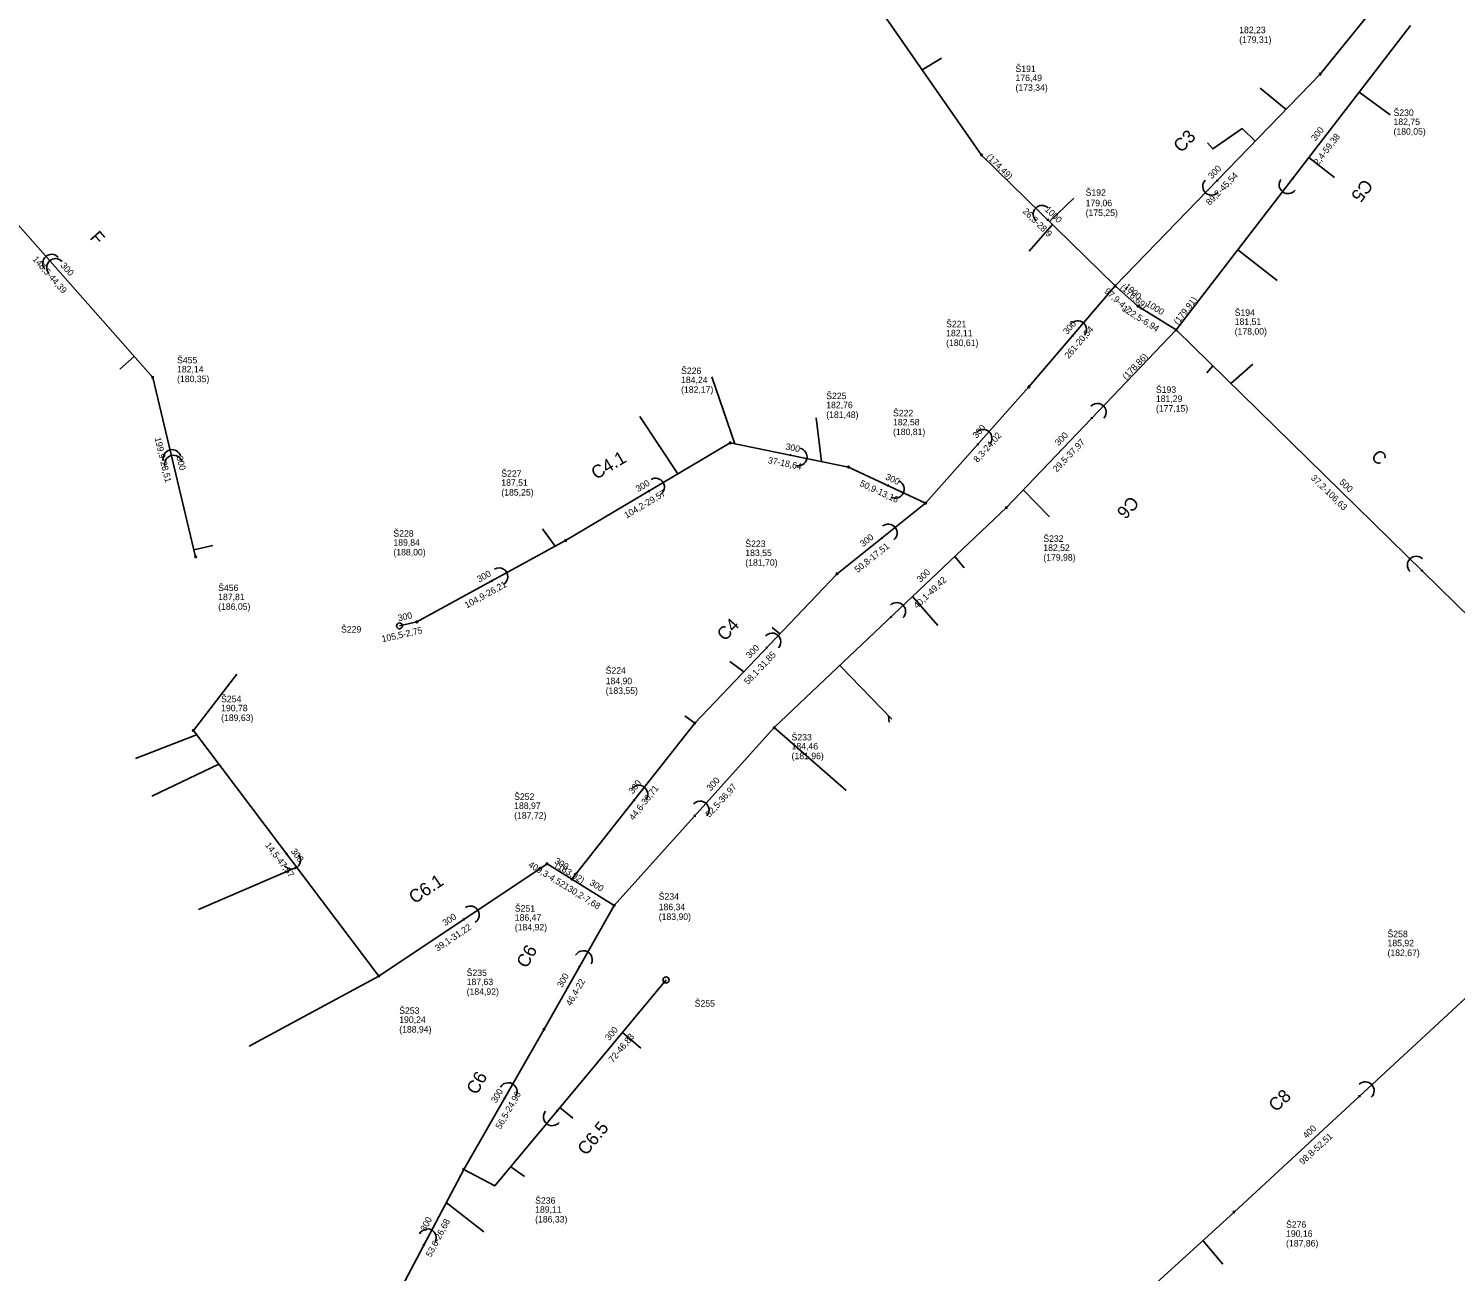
# Model space of a CAD drawing. Extents: x -548529 to -543591, y -1201432 to -1192608.
# Drawn here: x -547490.5 to -547270, y -1195800.5 to -1195608.4 of the extents above; entities that cross this region are included whole.
import ezdxf

# ---------------------------------------------------------------- set-up
doc = ezdxf.new("R2010")
doc.units = 0
for name, color, linetype in [('C3D_Bod-Značky', 7, 'Continuous'), ('C3D_Koridor', 7, 'Continuous'), ('C3D_Křižovatka', 7, 'Continuous'), ('C3D_Netisknutelná', 7, 'Continuous'), ('C3D_Podsestava', 7, 'Continuous'), ('C3D_PP-zobrazeni v PR', 7, 'Continuous'), ('C3D_PR-Popisek', 7, 'Continuous'), ('C3D_SPR-Popisek', 7, 'Continuous'), ('C3D_Tlakove_potrubi_Popis', 7, 'Continuous'), ('C3D_ZPR-Formaty', 7, 'Continuous')]:
    doc.layers.add(name, color=color, linetype=linetype)

# ---------------------------------------------------------------- blocks, each defined once
blk = doc.blocks.new('100')
at = {"layer": 'Defpoints'}
blk.add_circle((0, 0), 0.127, dxfattribs=at)
blk = doc.blocks.new('101')
at = {"layer": 'Defpoints'}
blk.add_circle((0, 0), 0.463, dxfattribs=at)
blk = doc.blocks.new('86')
at = {"layer": 'Defpoints'}
blk.add_lwpolyline([(0.08, 0.14), (0.19, 0), (0.08, -0.14)], dxfattribs=at)
blk.add_arc((1.37, 0), 1.37, 270, 90, dxfattribs=at)
blk = doc.blocks.new('91')
at = {"layer": 'Defpoints'}
blk.add_lwpolyline([(0.08, 0.14), (0.19, 0), (0.08, -0.14)], dxfattribs=at)
blk.add_arc((1.37, 0), 1.37, 270, 90, dxfattribs=at)
blk = doc.blocks.new('88')
at = {"layer": 'Defpoints'}
for centre in [(0.47, 0), (1.37, 0)]:
    blk.add_arc(centre, 1.37, 270, 90, dxfattribs=at)

msp = doc.modelspace()

# ---------------------------------------------------------------- linework, layer by layer
at = {"layer": 'C3D_Bod-Značky'}
for points in [[(-547343.222, -1195627.948), (-547378.023, -1195577.949)], [(-547261.272, -1195578.867), (-547290.91, -1195615.433)], [(-547276.928, -1195607.929), (-547313.169, -1195654.962)], [(-547290.91, -1195615.433), (-547322.568, -1195648.165)], [(-547322.568, -1195648.165), (-547343.222, -1195627.948)], [(-547335.918, -1195663.777), (-547322.568, -1195648.165)], [(-547319.066, -1195651.296), (-547322.568, -1195648.165)], [(-547313.169, -1195654.962), (-547319.066, -1195651.296)], [(-547339.386, -1195682.43), (-547313.169, -1195654.962)], [(-547237.001, -1195729.585), (-547313.169, -1195654.962)], [(-547351.862, -1195681.742), (-547335.918, -1195663.777)], [(-547407.485, -1195687.504), (-547382.048, -1195672.428)], [(-547382.048, -1195672.428), (-547363.782, -1195676.159)], [(-547363.782, -1195676.159), (-547351.862, -1195681.742)], [(-547375.25, -1195716.43), (-547339.386, -1195682.43)], [(-547365.556, -1195692.655), (-547351.862, -1195681.742)], [(-547430.477, -1195700.089), (-547407.485, -1195687.504)], [(-547387.512, -1195715.73), (-547365.556, -1195692.655)], [(-547433.16, -1195700.702), (-547430.477, -1195700.089)], [(-547406.517, -1195739.851), (-547387.512, -1195715.73)], [(-547399.992, -1195743.898), (-547375.25, -1195716.43)], [(-547465.003, -1195716.865), (-547436.327, -1195754.821)], [(-547436.327, -1195754.821), (-547410.36, -1195737.48)], [(-547410.36, -1195737.48), (-547406.517, -1195739.851)], [(-547406.517, -1195739.851), (-547399.992, -1195743.898)], [(-547410.818, -1195763.055), (-547399.992, -1195743.898)], [(-547391.973, -1195755.423), (-547402.576, -1195768.178), (-547418.429, -1195787.249), (-547423.237, -1195784.702)], [(-547304.215, -1195791.3), (-547265.674, -1195755.643)], [(-547423.237, -1195784.702), (-547410.818, -1195763.055)], [(-547435.695, -1195808.298), (-547423.237, -1195784.702)], [(-547340.806, -1195824.625), (-547304.215, -1195791.3)]]:
    msp.add_lwpolyline(points, dxfattribs=at)
at = {"layer": 'C3D_Koridor'}
for points in [[(-547352.385, -1195614.783), (-547349.399, -1195612.96)], [(-547296.187, -1195620.889), (-547300.174, -1195617.588)], [(-547284.875, -1195618.243), (-547280.095, -1195621.706)], [(-547300.935, -1195625.798), (-547302.956, -1195623.844), (-547307.511, -1195626.987), (-547308.321, -1195626.071)], [(-547292.655, -1195628.339), (-547288.712, -1195631.414)], [(-547332.727, -1195638.221), (-547328.975, -1195634.618)], [(-547332.245, -1195638.692), (-547335.878, -1195642.777)], [(-547303.619, -1195642.568), (-547297.54, -1195647.34)], [(-547474.142, -1195659.064), (-547476.389, -1195661.052)], [(-547307.497, -1195660.519), (-547308.409, -1195661.583)], [(-547304.705, -1195663.254), (-547301.324, -1195660.252)], [(-547381.331, -1195672.574), (-547384.9, -1195662.212)], [(-547390.127, -1195677.216), (-547396.022, -1195668.359)], [(-547367.951, -1195675.307), (-547368.802, -1195668.574)], [(-547336.774, -1195679.694), (-547332.727, -1195683.866)], [(-547409.111, -1195688.394), (-547411.068, -1195685.702)], [(-547464.915, -1195688.96), (-547461.997, -1195688.263)], [(-547347.345, -1195689.976), (-547345.934, -1195691.726)], [(-547353.883, -1195696.173), (-547349.965, -1195700.662)], [(-547374.381, -1195701.93), (-547375.571, -1195700.982)], [(-547379.974, -1195707.808), (-547382.141, -1195706.211)], [(-547365.109, -1195706.816), (-547357.1, -1195715.113)], [(-547465.003, -1195716.865), (-547458.264, -1195708.195)], [(-547387.512, -1195715.73), (-547389.076, -1195714.588)], [(-547357.584, -1195714.612), (-547357.517, -1195715.581)], [(-547375.25, -1195716.43), (-547364.156, -1195726.142)], [(-547464.506, -1195717.523), (-547473.969, -1195721.212)], [(-547461.049, -1195722.099), (-547471.434, -1195727.004)], [(-547449.038, -1195737.997), (-547464.186, -1195744.548)], [(-547436.327, -1195754.821), (-547456.362, -1195765.651)], [(-547398.72, -1195763.539), (-547395.893, -1195765.988)], [(-547408.372, -1195775.15), (-547406.369, -1195776.768)], [(-547415.97, -1195784.29), (-547413.84, -1195785.806)], [(-547425.936, -1195789.814), (-547420.136, -1195794.348)], [(-547309.05, -1195795.704), (-547305.929, -1195799.346)]]:
    msp.add_lwpolyline(points, dxfattribs=at)
at = {"layer": 'C3D_Podsestava'}
for points in [[(-547471.28, -1195662.3), (-547500.69, -1195629.05)], [(-547464.66, -1195690.03), (-547471.28, -1195662.3)]]:
    msp.add_lwpolyline(points, dxfattribs=at)

# ---------------------------------------------------------------- block references
at = {"layer": 'C3D_PP-zobrazeni v PR'}
for name, p, xscale, yscale, rotation in [('100', (-547290.91, -1195615.433), 1.0000000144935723, 1.0000000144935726, -130.99999910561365), ('100', (-547343.222, -1195627.948), 1.0000000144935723, 1.0000000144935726, 130.99999910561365), ('100', (-547322.568, -1195648.165), 1.0000000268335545, 1.0000000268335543, -176.00000028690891), ('100', (-547319.066, -1195651.296), 1.000000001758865, 1.000000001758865, 144.00000066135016), ('100', (-547313.169, -1195654.962), 1.0060666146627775, 1.0060666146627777, -167.3452647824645), ('100', (-547471.28, -1195662.3), 0.9999999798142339, 0.9999999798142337, -61.99999866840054), ('100', (-547335.918, -1195663.777), 1.0000000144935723, 1.0000000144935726, -130.99999910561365), ('100', (-547382.048, -1195672.428), 1.0073309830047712, 1.0073309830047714, -167.86109133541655), ('100', (-547363.782, -1195676.159), 1.033506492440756, 1.033506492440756, 156.95871826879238), ('100', (-547351.862, -1195681.742), 1.0000000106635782, 1.0000000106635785, -135.99999834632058), ('100', (-547339.386, -1195682.43), 0.999999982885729, 0.9999999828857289, -135), ('100', (-547407.485, -1195687.504), 0.9999999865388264, 0.9999999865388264, -149.99999955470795), ('100', (-547464.66, -1195690.03), 1.0000000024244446, 1.0000000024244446, -75.99999967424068), ('100', (-547365.556, -1195692.655), 1.00000000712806, 1.00000000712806, -136.99999943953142), ('101', (-547433.16, -1195700.702), 1.0028916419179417, 1.0028916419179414, -166.30279126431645), ('100', (-547430.477, -1195700.089), 1.0275072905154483, 1.027507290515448, -155.31089431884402), ('100', (-547465.003, -1195716.865), 1.000000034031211, 1.0000000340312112, 128.00000040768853), ('100', (-547387.512, -1195715.73), 1.0000000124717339, 1.0000000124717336, -130.0000013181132), ('100', (-547375.25, -1195716.43), 1.0000000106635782, 1.0000000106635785, -134.00000165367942), ('100', (-547410.36, -1195737.48), 1.00000001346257, 1.0000000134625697, -178.0000000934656), ('100', (-547406.517, -1195739.851), 1.0060666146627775, 1.0060666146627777, -167.3452647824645), ('100', (-547399.992, -1195743.898), 1.000000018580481, 1.000000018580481, -125.00000023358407), ('100', (-547436.327, -1195754.821), 1.008377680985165, 1.0083776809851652, 168.37362119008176), ('101', (-547391.973, -1195755.423), 1.000000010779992, 1.0000000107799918, 51.00000108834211), ('100', (-547410.818, -1195763.055), 1.0000000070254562, 1.0000000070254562, -118.99999892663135), ('100', (-547423.237, -1195784.702), 0.9999999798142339, 0.9999999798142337, -118.00000133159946), ('100', (-547304.215, -1195791.3), 1.00000000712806, 1.00000000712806, -136.99999943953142)]:
    msp.add_blockref(name, p, dxfattribs=dict(at, xscale=xscale, yscale=yscale, rotation=rotation))
at = {"layer": 'C3D_SPR-Popisek'}
for name, p, xscale, yscale, rotation in [('91', (-547295.048, -1195631.446), 0.9999999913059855, 0.9999999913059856, -127.00000193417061), ('91', (-547306.739, -1195631.799), 1.0000000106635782, 1.0000000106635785, -134.00000165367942), ('91', (-547332.895, -1195638.056), 1.0000000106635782, 1.0000000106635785, 135.99999834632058), ('88', (-547485.985, -1195645.675), 1.0000000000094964, 1.0000000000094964, 132.0000013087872), ('91', (-547329.243, -1195655.971), 1.0000000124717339, 1.0000000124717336, 49.99999868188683), ('91', (-547326.278, -1195668.696), 1.00000000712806, 1.00000000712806, 46.99999943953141), ('91', (-547343.89, -1195672.76), 1.0000000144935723, 1.0000000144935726, 49.00000089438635), ('88', (-547467.97, -1195676.165), 1.0000000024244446, 1.0000000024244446, 104.00000032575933), ('91', (-547372.915, -1195674.294), 1.0060666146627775, 1.0060666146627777, -12.654735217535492), ('91', (-547394.766, -1195679.966), 1.0000000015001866, 1.0000000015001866, 30.99999982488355), ('91', (-547357.822, -1195678.95), 1.0169562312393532, 1.016956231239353, -26.97601645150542), ('91', (-547358.709, -1195687.198), 1.000000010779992, 1.0000000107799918, 38.9999989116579), ('91', (-547275.085, -1195692.274), 1.0000000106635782, 1.0000000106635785, 135.99999834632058), ('91', (-547418.981, -1195693.796), 1.0037042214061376, 1.0037042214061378, 29.379208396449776), ('91', (-547357.318, -1195699.43), 1.0000000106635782, 1.0000000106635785, 44.00000165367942), ('91', (-547376.534, -1195704.192), 1.00000000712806, 1.00000000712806, 46.99999943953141), ('91', (-547397.015, -1195727.79), 1.000000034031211, 1.0000000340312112, 51.999999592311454), ('91', (-547387.621, -1195730.164), 1.0000000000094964, 1.0000000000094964, 47.99999869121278), ('86', (-547450.665, -1195735.843), 1.000000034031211, 1.0000000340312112, -51.999999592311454), ('86', (-547423.344, -1195746.15), 0.9999999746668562, 0.999999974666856, 34.00000045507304), ('91', (-547405.405, -1195753.476), 1.0000000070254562, 1.0000000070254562, 61.000001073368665), ('91', (-547417.028, -1195773.878), 1.0000000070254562, 1.0000000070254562, 61.000001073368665), ('86', (-547284.944, -1195773.472), 1.00000000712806, 1.00000000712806, 43.0000005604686), ('91', (-547408.676, -1195775.517), 1.000000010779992, 1.0000000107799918, -128.99999891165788), ('91', (-547429.466, -1195796.5), 0.9999999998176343, 0.9999999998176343, 63.00000066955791)]:
    msp.add_blockref(name, p, dxfattribs=dict(at, xscale=xscale, yscale=yscale, rotation=rotation))

# ---------------------------------------------------------------- texts
at = {"layer": 'C3D_Křižovatka'}
for s, p in [('Š191', (-547337.982, -1195615.118)), ('Š230', (-547279.578, -1195621.899)), ('Š192', (-547327.148, -1195634.225)), ('Š194', (-547304.119, -1195652.792)), ('Š221', (-547348.698, -1195654.557)), ('Š455', (-547467.52, -1195660.14)), ('Š226', (-547389.648, -1195661.788)), ('Š193', (-547316.286, -1195664.696)), ('Š225', (-547367.222, -1195665.669)), ('Š222', (-547356.902, -1195668.322)), ('Š227', (-547417.425, -1195677.664)), ('Š228', (-547434.097, -1195686.919)), ('Š223', (-547379.726, -1195688.515)), ('Š232', (-547333.686, -1195687.72)), ('Š456', (-547461.17, -1195695.33)), ('Š229', (-547442.18, -1195701.742)), ('Š224', (-547401.302, -1195708.09)), ('Š254', (-547460.713, -1195712.505)), ('Š233', (-547372.58, -1195718.41)), ('Š252', (-547415.44, -1195727.6)), ('Š234', (-547393.102, -1195743.018)), ('Š251', (-547415.337, -1195744.871)), ('Š258', (-547280.504, -1195748.823)), ('Š235', (-547422.778, -1195754.825)), ('Š255', (-547387.543, -1195759.553)), ('Š253', (-547433.197, -1195760.661)), ('Š236', (-547412.197, -1195790.012)), ('Š276', (-547296.175, -1195793.72))]:
    msp.add_text(s, height=1, dxfattribs=at).set_placement(p)
at = {"layer": 'C3D_Netisknutelná'}
for s, rotation, p in [('C3', 45.96, (-547312.363, -1195627.691)), ('C5', 232.38, (-547284.164, -1195631.5)), ('F', 311.49, (-547481.103, -1195640.775)), ('C4.1', 30.65, (-547402.789, -1195678.156)), ('C', 315.59, (-547283.188, -1195674.677)), ('C6', 227.82, (-547320.19, -1195680.491)), ('C4', 46.42, (-547382.876, -1195703.179)), ('C6.1', 33.74, (-547430.857, -1195743.736)), ('C6', 60.53, (-547413.481, -1195753.738)), ('C6', 60.16, (-547421.215, -1195773.295)), ('C8', 42.77, (-547297.755, -1195775.929)), ('C6.5', 50.26, (-547404.323, -1195782.681))]:
    msp.add_text(s, height=2, rotation=rotation, dxfattribs=at).set_placement(p)
at = {"layer": 'C3D_PR-Popisek'}
for s, rotation, p in [('300', 52.38, (-547291.627, -1195625.849)), ('300', 45.96, (-547307.638, -1195631.718)), ('1000', 315.61, (-547333.523, -1195636.459)), ('300', 311.49, (-547485.592, -1195645.069)), ('1000', 318.2, (-547321.275, -1195648.388)), ('1000', 328.13, (-547317.947, -1195651.174)), ('300', 49.47, (-547329.977, -1195655.758)), ('300', 48.41, (-547343.982, -1195671.814)), ('300', 348.46, (-547373.575, -1195673.444)), ('300', 46.33, (-547331.307, -1195672.948)), ('300', 283.43, (-547467.623, -1195674.583)), ('300', 30.65, (-547396.294, -1195680.061)), ('300', 334.9, (-547358.18, -1195678.013)), ('500', 315.59, (-547288.028, -1195678.609)), ('300', 38.55, (-547361.537, -1195688.56)), ('300', 28.69, (-547420.852, -1195694.022)), ('300', 43.47, (-547352.671, -1195694.067)), ('300', 12.87, (-547433.292, -1195700.012)), ('300', 46.42, (-547379.03, -1195705.806)), ('300', 51.76, (-547397.096, -1195726.766)), ('300', 47.99, (-547385.085, -1195726.309)), ('300', 307.07, (-547450.004, -1195735.557)), ('300', 328.33, (-547409.312, -1195737.301)), ('300', 328.19, (-547403.891, -1195740.663)), ('300', 33.74, (-547426.098, -1195747.143)), ('300', 60.53, (-547408.035, -1195756.697)), ('300', 50.26, (-547400.747, -1195764.887)), ('300', 60.16, (-547418.213, -1195774.543)), ('400', 42.77, (-547293.043, -1195780.006)), ('300', 62.17, (-547429.118, -1195794.348))]:
    msp.add_text(s, height=1, rotation=rotation, dxfattribs=at).set_placement(p)
at = {"layer": 'C3D_Tlakove_potrubi_Popis'}
for s, p in [('182,23 ', (-547303.42, -1195609.113)), ('(179,31)', (-547303.42, -1195610.613)), ('(173,34)', (-547337.982, -1195618.018)), ('176,49 ', (-547337.982, -1195616.518)), ('(180,05)', (-547279.578, -1195624.799)), ('182,75 ', (-547279.578, -1195623.299)), ('179,06 ', (-547327.148, -1195635.855)), ('(175,25)', (-547327.148, -1195637.355)), ('182,11 ', (-547348.698, -1195655.957)), ('(178,00)', (-547304.119, -1195655.692)), ('181,51 ', (-547304.119, -1195654.192)), ('(180,61)', (-547348.698, -1195657.457)), ('182,14 ', (-547467.52, -1195661.54)), ('(180,35)', (-547467.52, -1195663.04)), ('(182,17)', (-547389.648, -1195664.688)), ('184,24 ', (-547389.648, -1195663.188)), ('182,76 ', (-547367.222, -1195667.069)), ('181,29 ', (-547316.286, -1195666.096)), ('(181,48)', (-547367.222, -1195668.569)), ('(177,15)', (-547316.286, -1195667.596)), ('(180,81)', (-547356.902, -1195671.222)), ('182,58 ', (-547356.902, -1195669.722)), ('187,51 ', (-547417.425, -1195679.064)), ('(185,25)', (-547417.425, -1195680.564)), ('189,84 ', (-547434.097, -1195688.319)), ('182,52 ', (-547333.686, -1195689.12)), ('(188,00)', (-547434.097, -1195689.819)), ('(181,70)', (-547379.726, -1195691.415)), ('183,55 ', (-547379.726, -1195689.915)), ('(179,98)', (-547333.686, -1195690.62)), ('187,81 ', (-547461.17, -1195696.73)), ('(186,05)', (-547461.17, -1195698.23)), ('(183,55)', (-547401.302, -1195711.22)), ('184,90 ', (-547401.302, -1195709.72)), ('(189,63)', (-547460.713, -1195715.405)), ('190,78 ', (-547460.713, -1195713.905)), ('184,46 ', (-547372.58, -1195719.81)), ('(181,96)', (-547372.58, -1195721.31)), ('(187,72)', (-547415.44, -1195730.5)), ('188,97 ', (-547415.44, -1195729)), ('186,47 ', (-547415.337, -1195746.271)), ('(183,90)', (-547393.102, -1195746.148)), ('186,34 ', (-547393.102, -1195744.648)), ('(184,92)', (-547415.337, -1195747.771)), ('185,92 ', (-547280.504, -1195750.223)), ('(182,67)', (-547280.504, -1195751.723)), ('187,63 ', (-547422.778, -1195756.225)), ('(184,92)', (-547422.778, -1195757.725)), ('(188,94)', (-547433.197, -1195763.561)), ('190,24 ', (-547433.197, -1195762.061)), ('189,11 ', (-547412.197, -1195791.412)), ('(186,33)', (-547412.197, -1195792.912)), ('(187,86)', (-547296.175, -1195796.62)), ('190,16 ', (-547296.175, -1195795.12))]:
    msp.add_text(s, height=1, dxfattribs=at).set_placement(p)
at = {"layer": 'C3D_ZPR-Formaty'}
for s, rotation, p in [('2,4-59,38', 52.38, (-547291.217, -1195629.582)), ('  (174,49)   ', 315.61, (-547343.082, -1195627.805)), ('89,2-45,54', 45.96, (-547307.962, -1195635.796)), ('26,3-28,9', 315.61, (-547336.951, -1195636.745)), ('148,5-44,39', 311.49, (-547489.915, -1195644.09)), ('  (176,69)   ', 318.2, (-547322.435, -1195648.016)), ('97,9-4,7', 318.2, (-547324.35, -1195649.122)), ('  (179,91)   ', 52.38, (-547313.327, -1195654.84)), ('122,5-6,94', 328.13, (-547321.609, -1195651.947)), ('261-20,54', 49.47, (-547329.758, -1195659.49)), ('  (178,86)   ', 46.33, (-547321.393, -1195663.287)), ('199,9-28,51', 283.43, (-547470.991, -1195671.687)), ('8,3-24,02', 48.41, (-547343.837, -1195675.553)), ('29,5-37,97', 46.33, (-547331.599, -1195677.024)), ('37-18,64', 348.46, (-547376.299, -1195675.546)), ('50,9-13,16', 334.9, (-547362.136, -1195679.025)), ('37,2-106,63', 315.59, (-547292.42, -1195677.95)), ('104,2-29,57', 30.65, (-547398.068, -1195684.131)), ('50,8-17,51', 38.55, (-547362.378, -1195692.558)), ('104,9-26,21', 28.69, (-547422.758, -1195698.028)), ('40,1-49,42', 43.47, (-547353.174, -1195698.12)), ('105,5-2,75', 12.87, (-547435.781, -1195703.248)), ('58,1-31,85', 46.42, (-547379.317, -1195709.873)), ('44,6-30,71', 51.76, (-547397.006, -1195730.846)), ('52,5-36,97', 47.99, (-547385.263, -1195730.387)), ('14,5-47,57', 307.07, (-547453.98, -1195734.608)), ('409,3-4,52', 328.33, (-547413.358, -1195737.869)), ('  (183,92)   ', 328.19, (-547409.829, -1195737.561)), ('130,2-7,68', 328.19, (-547407.936, -1195741.203)), ('39,1-31,22', 33.74, (-547427.27, -1195751.056)), ('46,4-22', 60.53, (-547406.652, -1195759.543)), ('72-46,83', 50.26, (-547400.189, -1195768.282)), ('56,5-24,96', 60.16, (-547417.526, -1195778.572)), ('98,8-52,51', 42.77, (-547293.585, -1195784.053)), ('53,6-26,68', 62.17, (-547428.291, -1195798.348))]:
    msp.add_text(s, height=1, rotation=rotation, dxfattribs=at).set_placement(p)

doc.saveas('drawing.dxf')
